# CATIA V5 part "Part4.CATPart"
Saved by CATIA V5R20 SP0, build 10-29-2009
Part number: 小齿轮
Bounding box of the stored display mesh (mm): x -4 to 0, y -10 to 10, z -10 to 10
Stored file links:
  D:\CATIA Data\Part4.CATPart
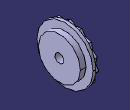
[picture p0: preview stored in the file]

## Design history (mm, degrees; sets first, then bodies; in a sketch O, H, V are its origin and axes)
Body1 (main body)
  Plane1: type Offset, RefPlane yz-plane, Offset 3, reversed
  Sketch1 on Plane1, origin (-3, 0, 0), H (0, 1, 0), V (0, 0, 1)
    circle A1 centre (0, 0) radius 10
  Pad1: profile Sketch1, direction (1, 0, 0), length 1
  Sketch2 on start face of Pad1, origin (-3, 0, 0), H (0, -1, 0), V (0, 0, 1)
    arc A1 centre (0, 0) radius 9 from (1.8491, 8.808) to (-1.8491, 8.808) ccw
    line L1 (1.8491, 8.808) -> (0, 10)
    point P2 (0, 10)
    line L2 (0, 10) -> (-1.8491, 8.808)
    radius A1 = 9
    distance P2 H = 10
    length L2 = 2.2
    length L1 = 2.2
    coincidence: P2 V
  Pad2: profile Sketch2, direction (-1, 0, 0), length 1
  Sketch3 on zx-plane, origin (0, 0, 0), H (-1, 0, 0), V (0, 0, 1)
    line L1 (-10, 0) -> (20, 0)
    horizontal: L1 H
  CircPattern1: of Pad2, instances 15, angular step 24, axis from Sketch3.L1
  Sketch4 on end face of Pad1, origin (-2, 0, 0), H (0, 1, 0), V (0, 0, 1)
    circle A1 centre (0, 0) radius 7.5
    radius A1 = 7.5
  Pad3: profile Sketch4, direction (1, 0, 0), length 2
  Sketch5 on end face of Pad3, origin (0, 0, 0), H (0, 1, 0), V (0, 0, 1)
    point P1 (0, 0)
  Hole1: placed by Sketch5, at (0, 0, 0) direction (-1, 0, 0), diameter 3.2, through (limit type 6)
